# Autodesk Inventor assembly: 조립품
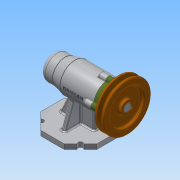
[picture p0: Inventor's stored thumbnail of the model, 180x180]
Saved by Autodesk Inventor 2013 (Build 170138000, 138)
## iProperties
Created: 2019-12
Part Number: 조립품
Document SubType Name: Assembly
Designer: Administrator
Author: Administrator
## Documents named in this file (12)
- C:\Users\Administrator\Desktop\491204V1027\조립품.iam
- C:\Users\Administrator\Desktop\491204V1027\본체.ipt
- C:\Users\Administrator\Desktop\491204V1027\축.ipt
- C:\Users\Administrator\Desktop\491204V1027\커버.ipt
- C:\Users\Administrator\Desktop\491204V1027\베어링 6004.ipt
- C:\Users\Administrator\Desktop\491204V1027\어댑터슬리브.ipt
- C:\Users\Administrator\Desktop\491204V1027\베어링 51202.ipt
- C:\Users\Administrator\Desktop\491204V1027\오일 실.ipt
- C:\Users\Administrator\Desktop\491204V1027\V벨트풀리.ipt
- C:\Users\Administrator\Desktop\491204V1027\키 5 x 5 x 16.ipt
- C:\Users\Administrator\Desktop\491204V1027\멈춤나사 M3.ipt
- C:\Users\Administrator\Desktop\491204V1027\볼트 M4.ipt
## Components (1 placed, 1 different names)
1. V벨트풀리:1 — 각도:2, 플러쉬:1
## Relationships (2: Angle 1, Flush 1)
- 각도:2 [Angle]: V벨트풀리:1
- 플러쉬:1 [Flush]: V벨트풀리:1
